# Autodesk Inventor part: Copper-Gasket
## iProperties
Shininess: 64.0
Length Units: 11269
Angle Units: 11279
Time Units: 11290
Mass Units: 11283
Length Display Precision: 3
Angle Display Precision: 2
Compacted: True
Part Number: Copper-Gasket
Document SubType Name: Modeling
Created: 2004-01
Designer: Administrator
Manufacturer: Standard
Standards Organization: Custom
Density: 1 g/cm^3
Density: 0.0
Volumn: 0.0
Area: 0.0
PropertySet Name: Model Information
Control State: 0
Master: False
Checked Out: False
Author: Administrator
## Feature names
1. Revolution1
2. Chamfer1
